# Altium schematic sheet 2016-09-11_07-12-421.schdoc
size 351 x 190 mm; SheetNumber: 1; SheetTotal: 1
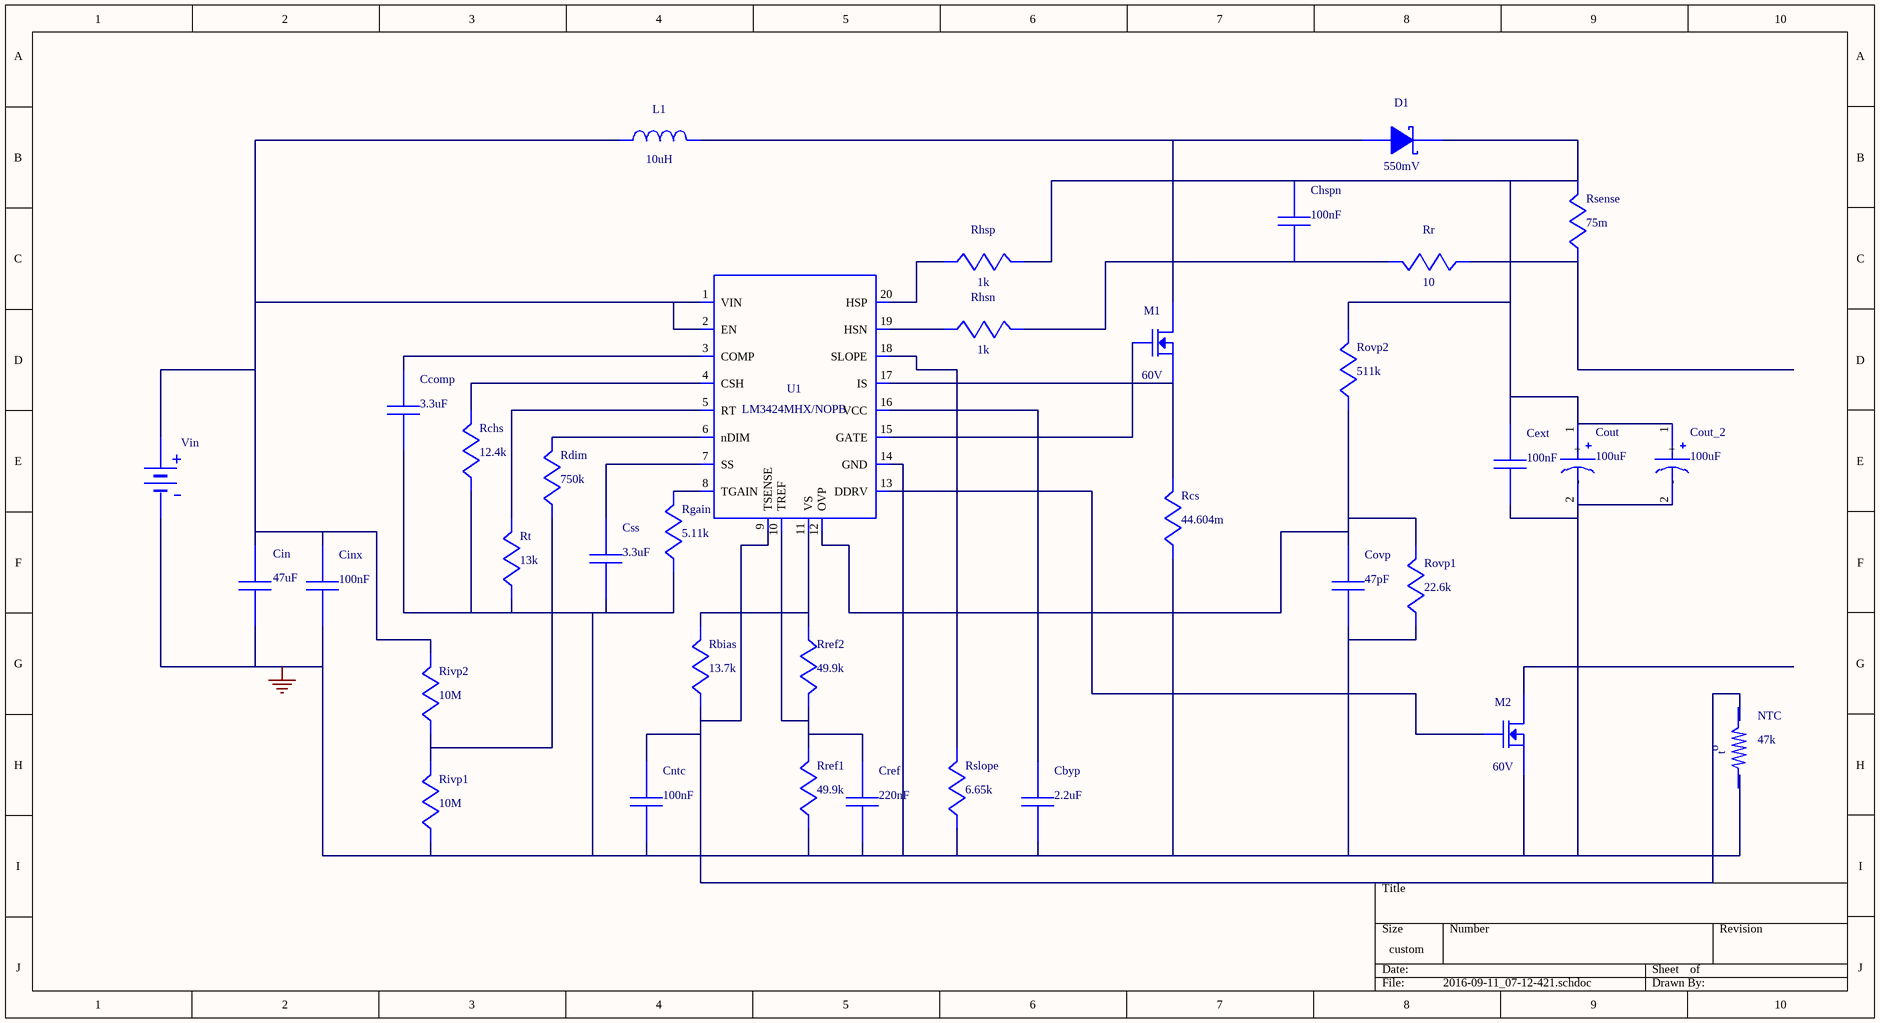
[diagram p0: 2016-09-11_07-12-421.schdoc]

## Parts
Cbyp  value 2.2uF  (hidden comment: EMK212B7225KG-T)
Ccomp  value 3.3uF  (hidden comment: GRM32NR71C335KA01L)
Cext  value 100nF  (hidden comment: C0805C104K5RACTU)
Chspn  value 100nF  (hidden comment: GRM21BR71E104KA01L)
Cin  value 47uF  (hidden comment: C3216X5R1E476M160AC)
Cinx  value 100nF  (hidden comment: C0603C104K5RACTU)
Cntc  value 100nF  (hidden comment: GRM21BR71E104KA01L)
Cout  value 100uF  (hidden comment: EEHZA1H101P)
Cout_2  value 100uF  (hidden comment: EEHZA1H101P)
Covp  value 47pF  (hidden comment: C0805C470K5GACTU)
Cref  value 220nF  (hidden comment: GRM155C80G224KE01D)
Css  value 3.3uF  (hidden comment: GRM32NR71C335KA01L)
D1  value 550mV  (hidden comment: B540C-13-F)
L1  value 10uH  (hidden comment: SDR1307-100ML)
M1  value 60V  (hidden comment: CSD18537NQ5A)
M2  value 60V  (hidden comment: CSD18537NQ5A)
NTC  value 47k  (hidden comment: NCP15WB473E03RC)
Rbias  value 13.7k  (hidden comment: CRCW040213K7FKED)
Rchs  value 12.4k  (hidden comment: CRCW040212K4FKED)
Rcs  value 44.604m  (hidden comment: CUSTOM1)
Rdim  value 750k  (hidden comment: CRCW0402750KFKED)
Rgain  value 5.11k  (hidden comment: CRCW04025K11FKED)
Rhsn  value 1k  (hidden comment: CRCW04021K00FKED)
Rhsp  value 1k  (hidden comment: CRCW04021K00FKED)
Rivp1  value 10M  (hidden comment: CRCW040210M0FKED)
Rivp2  value 10M  (hidden comment: CRCW040210M0FKED)
Rovp1  value 22.6k  (hidden comment: CRCW040222K6FKED)
Rovp2  value 511k  (hidden comment: CRCW0402511KFKED)
Rr  value 10  (hidden comment: CRCW040210R0FKED)
Rref1  value 49.9k  (hidden comment: CRCW040249K9FKED)
Rref2  value 49.9k  (hidden comment: CRCW040249K9FKED)
Rsense  value 75m  (hidden comment: CSR1206FK75L0)
Rslope  value 6.65k  (hidden comment: CRCW04026K65FKED)
Rt  value 13k  (hidden comment: CRCW040213K0FKED)
U1  LM3424MHX/NOPB
Vin  WB_BATTERY  (value not drawn)

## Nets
0: Cbyp.2 Ccomp.2 Cext.2 Cin.2 Cinx.2 Cntc.2 Cout.2(-) Cout_2.2(-) Covp.2 Cref.2 Css.2 M2.1(Source) M2.2(Source) M2.3(Source) Rchs.2 Rcs.1 Rgain.2 Rivp1.2 Rovp1.2 Rref1.2 Rslope.2 Rt.2 U1.14(GND) U1.21(DAP) Vin.2(-)
NetCbyp_1: Cbyp.1 U1.16(VCC)
NetCcomp_1: Ccomp.1 U1.3(COMP)
NetCext_1: Cext.1 Chspn.1 Cout.1(+) Cout_2.1(+) D1.1(K) Rhsp.1 Rovp2.1 Rsense.1
NetChspn_2: Chspn.2 Rhsn.1 Rr.1
NetCin_1: Cin.1 Cinx.1 L1.1 Rivp2.1 U1.1(VIN) U1.2(EN) Vin.1(+)
NetCntc_1: Cntc.1 Rbias.2 U1.9(TSENSE)
NetCovp_1: Covp.1 Rovp1.1 Rovp2.2 U1.12(OVP)
NetCref_1: Cref.1 Rref1.1 Rref2.1 U1.10(TREF)
NetCss_1: Css.1 U1.7(SS)
NetD1_2: D1.2(A) L1.2 M1.5(Drain) M1.6(Drain) M1.7(Drain) M1.8(Drain) M1.9(Drain)
NetM1_1: M1.1(Source) M1.2(Source) M1.3(Source) Rcs.2 U1.17(IS)
NetM1_4: M1.4(Gate) U1.15(GATE)
NetM2_4: M2.4(Gate) U1.13(DDRV)
NetM2_5: M2.5(Drain) M2.6(Drain) M2.7(Drain) M2.8(Drain) M2.9(Drain)
NetRbias_1: Rbias.1 Rref2.2 U1.11(VS)
NetRchs_1: Rchs.1 U1.4(CSH)
NetRdim_1: Rdim.1 U1.6(nDIM)
NetRdim_2: Rdim.2 Rivp1.1 Rivp2.2
NetRgain_1: Rgain.1 U1.8(TGAIN)
NetRhsn_2: Rhsn.2 U1.19(HSN)
NetRhsp_2: Rhsp.2 U1.20(HSP)
NetRr_2: Rr.2 Rsense.2
NetRslope_1: Rslope.1 U1.18(SLOPE)
NetRt_1: Rt.1 U1.5(RT)

Not connected (* = marked no-connect by the designer): NTC 1 2

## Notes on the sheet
- (near NTC) o
- (near NTC) t

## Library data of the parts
Cbyp = EMK212B7225KG-T: Manufacturer Name: Taiyo Yuden
Ccomp Css = GRM32NR71C335KA01L: GRM32NR71C335KA0; Manufacturer Name: MuRata
Cext = C0805C104K5RACTU: Manufacturer Name: Kemet
Chspn Cntc = GRM21BR71E104KA01L: GRM21BR71E104KA0; Manufacturer Name: MuRata
Cin = C3216X5R1E476M160AC: C3216X5R1E476M16; Manufacturer Name: TDK
Cinx = C0603C104K5RACTU: Manufacturer Name: Kemet
Cout Cout_2 = EEHZA1H101P: Manufacturer Name: Panasonic
Covp = C0805C470K5GACTU: Manufacturer Name: Kemet
Cref = GRM155C80G224KE01D: GRM155C80G224KE0; Manufacturer Name: MuRata
D1 = B540C-13-F: Manufacturer Name: Diodes Inc.
L1 = SDR1307-100ML: Manufacturer Name: Bourns
M1 M2 = CSD18537NQ5A: Manufacturer Name: Texas Instruments
NTC = NCP15WB473E03RC: Manufacturer Name: MuRata
Rbias = CRCW040213K7FKED: Manufacturer Name: Vishay-Dale
Rchs = CRCW040212K4FKED: Manufacturer Name: Vishay-Dale
Rcs = CUSTOM1: Manufacturer Name: CUSTOM
Rdim = CRCW0402750KFKED: Manufacturer Name: Vishay-Dale
Rgain = CRCW04025K11FKED: Manufacturer Name: Vishay-Dale
Rhsn Rhsp = CRCW04021K00FKED: Manufacturer Name: Vishay-Dale
Rivp1 Rivp2 = CRCW040210M0FKED: Manufacturer Name: Vishay-Dale
Rovp1 = CRCW040222K6FKED: Manufacturer Name: Vishay-Dale
Rovp2 = CRCW0402511KFKED: Manufacturer Name: Vishay-Dale
Rr = CRCW040210R0FKED: Manufacturer Name: Vishay-Dale
Rref1 Rref2 = CRCW040249K9FKED: Manufacturer Name: Vishay-Dale
Rsense = CSR1206FK75L0: Manufacturer Name: Stackpole Electronics Inc
Rslope = CRCW04026K65FKED: Manufacturer Name: Vishay-Dale
Rt = CRCW040213K0FKED: Manufacturer Name: Vishay-Dale
U1 = LM3424MHX/NOPB: Manufacturer Name: Texas Instruments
